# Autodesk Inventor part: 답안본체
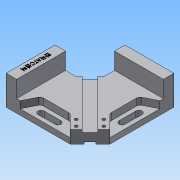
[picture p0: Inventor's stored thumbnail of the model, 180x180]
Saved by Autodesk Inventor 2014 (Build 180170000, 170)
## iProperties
Created: 2019-04
Part Number: 답안본체
Material: 알루미늄 6061
Document SubType Name: Modeling
Designer: NET
Density: 2.71 g/cm^3
Appearance: 알루미늄 - 평지
Mass: 603.738 g
Surface Area: 426.536 cm^2
Volume: 222.782 cm^3
Author: NET
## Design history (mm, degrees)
sketch "스케치2"
  geometry: L1 (60, -60)-(-60, -60); L2 (-60, -60)-(-60, 60); L3 (-60, 60)-(60, 60); L4 (60, 60)-(60, -60); L5 (60, -60)-(-60, 60); L6 (-60, -60)-(60, 60); 1 further point
  constraints: 12 end point, 2 midpoint, 2 parallel, 1 horizontal, 1 perpendicular
  dimensions: "d1" = 120 distance of L2.end L3.end; "d2" = 120 distance of L1.end L2.end
extrude "돌출1" new body sketch "스케치2" stored distance "d3" = 42; taper "d4" = 0 deg
sketch "스케치3"
  geometry: L1 (60, 60)-(-60, 60) reference; L2 (-60, 60)-(-60, -60) reference; L3 (60, -60)-(-45, -60); L4 (-45, -60)-(-45, 45); L5 (-45, 45)-(60, 45); L6 (60, 45)-(60, -60); 1 further point
  constraints: 8 end point, 2 parallel, 1 horizontal, 1 perpendicular
  dimensions: "d5" = 15 distance between parallel lines of L5 L1; "d6" = 15 distance between parallel lines of L2 L4
extrude "돌출2" cut sketch "스케치3" distance "d7" = 24; taper "d8" = 0 deg
sketch "스케치5"
  geometry: L1 (60, 45)-(60, -60) reference; L2 (60, -60)-(-45, -60) reference; L3 (60, -31.716)-(31.716, -60); L4 (60, -60)-(-60, -60) reference; 1 further point
  constraints: 2 end point, 2 point on line
  dimensions: "d11" = 20 distance from line of L1.end L3; "d12" = 45 deg angle of L2 L3
extrude "돌출3" cut sketch "스케치5" distance "d13" = 24; taper "d14" = 0 deg
sketch "스케치6"
  geometry: L1 (-45, 45)-(60, 45) reference; L2 (60, 60)-(-60, 60) reference; L3 (-60, 60)-(-60, -60) reference; L4 (-60, -60)-(-45, -60) reference; L5 (31.716, -60)-(60, -31.716) reference; L6 (-10, 29.806)-(-29.806, 10); L7 (-29.806, 10)-(-60, 10); L8 (-10, 60)-(-10, 29.806); 1 further point
  constraints: 6 end point, 2 parallel, 2 point on line, 1 perpendicular
  dimensions: "d16" = 93 distance between parallel lines of L5 L6; "d17" = 50 distance between parallel lines of L3 L8; "d18" = 50 distance between parallel lines of L7 L2
extrude "돌출4" cut sketch "스케치6" stored distance "d19" = 24; taper "d20" = 0 deg
sketch "스케치7"
  geometry: L1 (31.716, -60)-(60, -31.716) reference; L2 (-10, 29.806)-(-29.806, 10) reference; L3 (-25.56, 14.246)-(40.201, -51.515); L4 (-14.246, 25.56)-(51.515, -40.201); L5 (-25.56, 14.246)-(-14.246, 25.56); L6 (51.515, -40.201)-(40.201, -51.515); L7 (-19.903, 19.903)-(45.858, -45.858); 1 further point
  constraints: 10 end point, 5 point on line, 2 collinear, 2 midpoint, 2 perpendicular
  dimensions: "d21" = 16 distance between parallel lines of L3 L4
extrude "돌출5" cut sketch "스케치7" distance "d22" = 3.5; taper "d23" = 0 deg
sketch "스케치8"
  geometry: L1 (60, 10)-(29.806, 10) reference; L2 (-60, -31.716)-(-31.716, -60) reference; L3 (-31.716, -60)-(60, -60) reference; L4 (60, -60)-(60, 10) reference; L5 (28.643, 37.128)-(-50.101, -41.615); L6 (37.128, 28.643)-(-41.615, -50.101); L7 (-50.101, -41.615)-(-41.615, -50.101); L8 (19.906, 19.906)-(-45.858, -45.858); L9 (28.643, 37.128)-(37.128, 28.643); L10 (14.246, 25.56)-(-51.515, -40.201) reference; 3 further points
  constraints: 10 end point, 4 point on line, 3 perpendicular, 2 midpoint, 1 collinear
  dimensions: "d24" = 12 distance between parallel lines of L6 L5
extrude "돌출6" cut sketch "스케치8" distance "d25" = 3; taper "d26" = 0 deg
sketch "스케치10"
  geometry: L1 (40.201, -51.515)-(-25.56, 14.246) reference; L2 (31.716, -60)-(-45, -60) reference; L3 (-60, 10)-(-60, -60) reference; L4 (-60, -60)-(-45, -60) reference; L5 (-60, -60)-(-40, -60); L6 (31.716, -60)-(-60, -60) reference; L7 (-40, -60)-(-30, -40); L8 (-30, -40)-(11.716, -40); L9 (11.716, -40)-(31.716, -60); 1 further point
  constraints: 8 end point, 2 parallel, 1 point on line
  dimensions: "d27" = 20 distance of L3.end L5.end; "d28" = 30 horizontal distance of L3.end L7.end; "d29" = 20 distance between parallel lines of L2 L8
extrude "돌출7" cut sketch "스케치10" distance "d30" = 10; taper "d31" = 0 deg
sketch "스케치11"
  geometry: L1 (31.716, -60)-(-40, -60) reference; L2 (-20, -50)-(4, -50); L3 (-20, -54.5)-(4, -54.5); L4 (4, -45.5)-(-20, -45.5); L5 (-60, 10)-(-60, -60) reference; A1 r 4.5 centre (-20, -50) between (-20, -45.5) and (-20, -54.5); A2 r 4.5 centre (4, -50) between (4, -54.5) and (4, -45.5); 2 further points
  constraints: 8 end point, 4 point on circle, 4 tangent, 2 centre point, 2 parallel, 1 midpoint
  dimensions: "d32" = 24 distance of L2.start L2.end; "d33" = 4.5 radius of A1; "d34" = 10 distance between parallel lines of L1 L2; "d35" = 40 distance from line of L5 L2.start
extrude "돌출8" cut sketch "스케치11" distance "d36" = 10; taper "d37" = 0 deg
node "작업 평면1"
sketch "스케치12"
  geometry: L1 (24.146, 15.66)-(-41.615, -50.101) reference; L2 (-41.615, -50.101)-(-31.716, -60) reference; L3 (15.66, 24.146)-(24.146, 15.66) reference; L4 (-31.716, -51.515)-(-41.615, -41.615); L5 (-41.615, -41.615)-(-48.333, -48.333); L6 (-41.615, -50.101)-(-50.101, -41.615) reference; L7 (-23.23, -43.029)-(-33.13, -33.13); L8 (-33.13, -33.13)-(-41.615, -41.615); L9 (-50.101, -41.615)-(-41.615, -50.101); 3 further points
  constraints: 10 end point, 3 midpoint, 2 parallel, 2 perpendicular, 1 collinear, 1 point on line
  dimensions: "d38" = 6 distance from line of L2 L4.start; "d40" = 14 distance of L4.start L4.end; "d41" = 90 deg angle of L6 L5; "d42" = 12 distance of L4.start L7.start
hole "구멍1" sketch "스케치12" at (-31.716, -51.515), (-23.23, -43.029) diameter "d43" = 4.5; stored, may be unused: countersink angle "d47" = 90 deg, drill point angle "d49" = 118 deg; dims "d44" = 6, "d45" = 8, "d46" = 10, "d48" = 8
fillet "모깎기1" dims "d50" = 5
sketch "스케치13"
  geometry: L1 (-45, 10)-(-60, 10) reference; L2 (-60, 10)-(-60, -60) reference; 2 further points
  constraints: 1 other
  dimensions: "d51" = 7.5 distance from line of L2 point (-52.5, -25); "d52" = 35 distance from line of L1 point (-52.5, -25)
feature "엠보싱1" sketch "스케치13" dims "d1" = 120, "d2" = 120, "d53" = 0.5, "d54" = 0
node "솔리드1"
mirror "대칭1"
mirror "대칭2"
